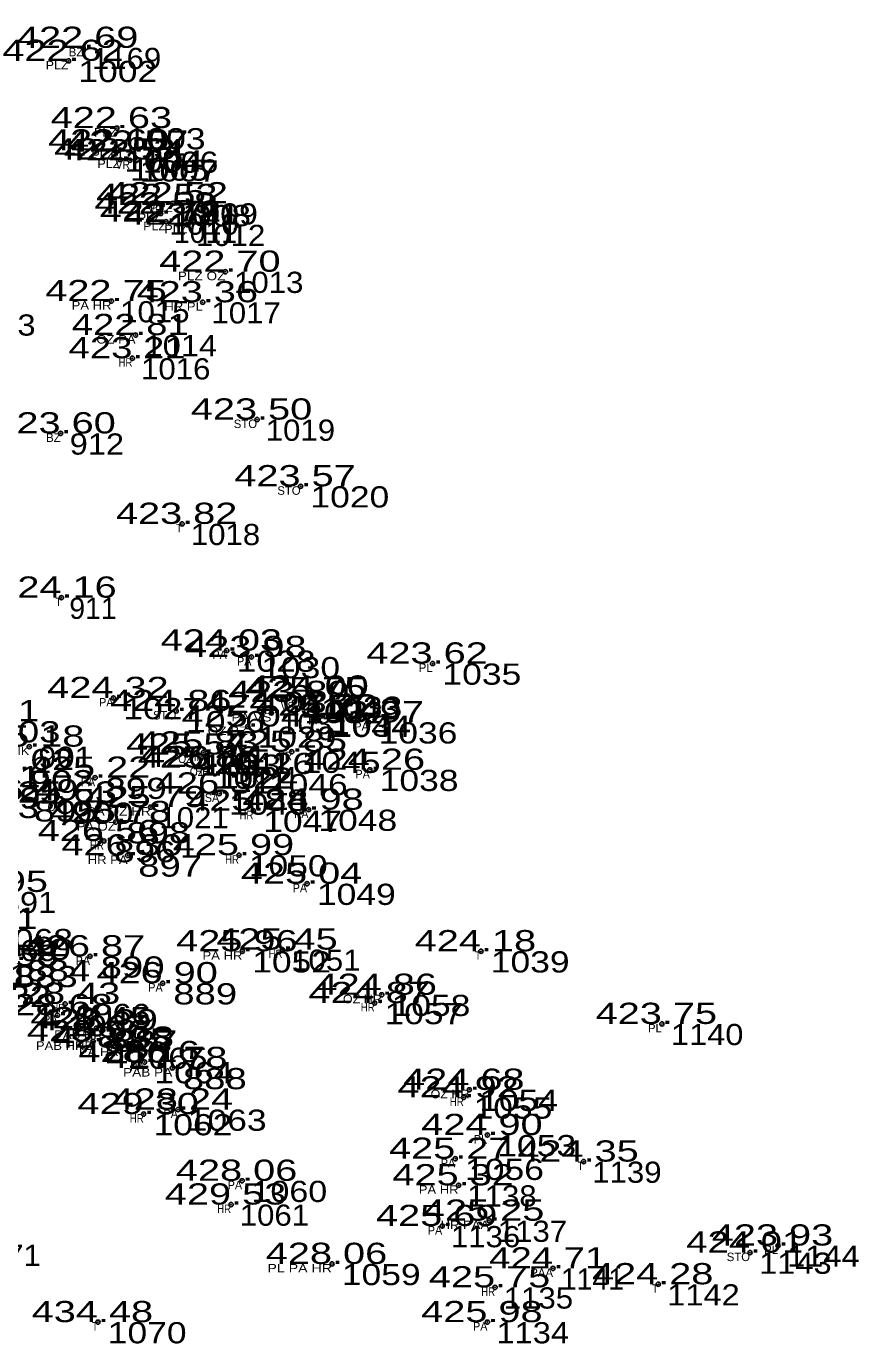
# Model space of a CAD drawing. Extents: x -639390 to -639074, y -1138747 to -1138358.
# Drawn here: x -639121.42 to -639091.98, y -1138695.49 to -1138648.89 of the extents above; entities that cross this region are included whole.
import ezdxf
from ezdxf.enums import TextEntityAlignment as Align

# ---------------------------------------------------------------- set-up
doc = ezdxf.new("R2010")
doc.units = 0
doc.header["$LTSCALE"] = 0.3
doc.header["$PDMODE"] = 32
doc.header["$PDSIZE"] = 0.15
for name, color, linetype in [('11', 7, 'Continuous'), ('12', 7, 'Continuous'), ('13', 7, 'Continuous'), ('57', 7, 'Continuous')]:
    doc.layers.add(name, color=color, linetype=linetype)

msp = doc.modelspace()

# ---------------------------------------------------------------- linework, layer by layer
at = {"layer": '11'}
for p in [(-639119.41, -1138649.65), (-639119.93, -1138650.11), (-639118.22, -1138652.49), (-639118.31, -1138653.28), (-639118.1, -1138653.6), (-639117.76, -1138653.63), (-639117.64, -1138653.32), (-639116.67, -1138655.51), (-639116.61, -1138655.21), (-639116.24, -1138655.15), (-639116.48, -1138655.8), (-639115.73, -1138655.91), (-639114.38, -1138657.57), (-639118.41, -1138658.61), (-639115.18, -1138658.65), (-639117.56, -1138659.81), (-639117.67, -1138660.63), (-639113.26, -1138662.8), (-639120.21, -1138663.29), (-639111.72, -1138665.16), (-639115.91, -1138666.49), (-639120.18, -1138669.1), (-639114.33, -1138670.97), (-639113.46, -1138671.2), (-639107.05, -1138671.43), (-639118.34, -1138672.65), (-639111.35, -1138672.66), (-639111.26, -1138672.6), (-639116.12, -1138673.11), (-639112.75, -1138673.18), (-639111.94, -1138672.79), (-639113.59, -1138673.66), (-639110.96, -1138673.28), (-639110.95, -1138673.27), (-639109.31, -1138673.51), (-639121.32, -1138674.37), (-639115.16, -1138674.58), (-639112.03, -1138674.55), (-639115.55, -1138674.65), (-639114.95, -1138675.09), (-639118.99, -1138675.47), (-639115.14, -1138675.11), (-639113.19, -1138675.34), (-639109.27, -1138675.19), (-639114.6, -1138676.03), (-639120.17, -1138676.35), (-639117.02, -1138676.51), (-639113.39, -1138676.64), (-639111.44, -1138676.6), (-639118.26, -1138677.04), (-639118.68, -1138677.71), (-639117.84, -1138678.22), (-639113.9, -1138678.21), (-639111.49, -1138679.22), (-639113.78, -1138681.61), (-639112.36, -1138681.55), (-639105.34, -1138681.61), (-639119.17, -1138681.79), (-639116.6, -1138682.74), (-639120.05, -1138683.47), (-639109.1, -1138683.44), (-639108.85, -1138683.15), (-639120.32, -1138683.87), (-639118.94, -1138684.33), (-639118.72, -1138684.41), (-639098.94, -1138684.18), (-639119.06, -1138684.8), (-639118.15, -1138685.02), (-639117.24, -1138685.53), (-639116.26, -1138685.74), (-639105.75, -1138686.51), (-639116.06, -1138687.21), (-639105.95, -1138686.78), (-639117.27, -1138687.37), (-639105.11, -1138688.11), (-639106.25, -1138688.95), (-639101.71, -1138689.05), (-639113.79, -1138689.73), (-639106.13, -1138689.89), (-639114.18, -1138690.57), (-639106.71, -1138691.33), (-639105.05, -1138691.14), (-639095.82, -1138692.27), (-639094.83, -1138692.02), (-639110.61, -1138692.67), (-639102.79, -1138692.83), (-639104.84, -1138693.5), (-639099.07, -1138693.39), (-639118.89, -1138694.73), (-639105.11, -1138694.73)]:
    msp.add_point(p, dxfattribs=at)

# ---------------------------------------------------------------- texts
at = {"layer": '12'}
for s, width, p in [('422.69 ', 1.4, (-639119.41, -1138649.65)), ('422.62 ', 1.4, (-639119.93, -1138650.11)), ('422.63 ', 1.4, (-639118.22, -1138652.49)), ('422.60 ', 1.4, (-639118.31, -1138653.28)), ('422.57 ', 1.4, (-639117.64, -1138653.32)), ('422.53 ', 1.4, (-639118.1, -1138653.6)), ('422.54 ', 1.4, (-639117.76, -1138653.63)), ('422.53 ', 1.4, (-639116.61, -1138655.21)), ('422.52 ', 1.4, (-639116.24, -1138655.15)), ('422.58 ', 1.4, (-639116.67, -1138655.51)), ('422.72 ', 1.4, (-639116.48, -1138655.8)), ('422.81 ', 1.35, (-639115.729, -1138655.91)), ('422.70 ', 1.4, (-639114.38, -1138657.57)), ('422.75 ', 1.4, (-639118.41, -1138658.61)), ('423.36 ', 1.4, (-639115.179, -1138658.65)), ('422.81 ', 1.35, (-639117.559, -1138659.81)), ('423.21 ', 1.35, (-639117.669, -1138660.63)), ('423.50 ', 1.4, (-639113.26, -1138662.8)), ('423.60 ', 1.4, (-639120.21, -1138663.29)), ('423.57 ', 1.4, (-639111.72, -1138665.16)), ('423.82 ', 1.4, (-639115.91, -1138666.49)), ('424.16 ', 1.4, (-639120.179, -1138669.1)), ('424.03 ', 1.4, (-639114.33, -1138670.97)), ('423.98 ', 1.4, (-639113.46, -1138671.2)), ('423.62 ', 1.4, (-639107.05, -1138671.43)), ('424.32 ', 1.4, (-639118.34, -1138672.65)), ('423.89 ', 1.4, (-639111.94, -1138672.79)), ('425.75 ', 1.4, (-639111.35, -1138672.66)), ('424.00 ', 1.4, (-639111.26, -1138672.6)), ('424.86 ', 1.4, (-639116.119, -1138673.11)), ('424.03 ', 1.4, (-639112.75, -1138673.18)), ('425.72 ', 1.4, (-639110.96, -1138673.28)), ('424.22 ', 1.4, (-639110.95, -1138673.27)), ('425.01 ', 1.35, (-639122.849, -1138673.47)), ('425.04 ', 1.4, (-639113.59, -1138673.66)), ('423.97 ', 1.4, (-639109.31, -1138673.51)), ('425.18 ', 1.4, (-639121.32, -1138674.37)), ('425.57 ', 1.4, (-639115.55, -1138674.65)), ('425.83 ', 1.4, (-639115.16, -1138674.58)), ('425.85 ', 1.4, (-639112.03, -1138674.55)), ('425.62 ', 1.4, (-639121.68, -1138675.2)), ('425.86 ', 1.4, (-639115.139, -1138675.11)), ('426.14 ', 1.4, (-639114.95, -1138675.09)), ('424.26 ', 1.4, (-639109.269, -1138675.19)), ('425.22 ', 1.4, (-639118.99, -1138675.47)), ('426.16 ', 1.4, (-639113.189, -1138675.34)), ('426.41 ', 1.35, (-639122.799, -1138675.81)), ('426.31 ', 1.35, (-639114.599, -1138676.03)), ('426.49 ', 1.4, (-639121.53, -1138676.27)), ('425.63 ', 1.4, (-639120.17, -1138676.35)), ('425.79 ', 1.4, (-639117.02, -1138676.51)), ('425.88 ', 1.4, (-639113.39, -1138676.64)), ('424.98 ', 1.4, (-639111.44, -1138676.6)), ('425.78 ', 1.4, (-639118.26, -1138677.04)), ('426.56 ', 1.4, (-639118.679, -1138677.71)), ('426.30 ', 1.4, (-639117.84, -1138678.22)), ('425.99 ', 1.4, (-639113.9, -1138678.21)), ('426.95 ', 1.4, (-639122.61, -1138679.51)), ('425.04 ', 1.4, (-639111.49, -1138679.22)), ('428.41 ', 1.35, (-639122.909, -1138680.82)), ('426.87 ', 1.4, (-639119.17, -1138681.79)), ('425.96 ', 1.4, (-639113.779, -1138681.61)), ('425.45 ', 1.4, (-639112.36, -1138681.55)), ('424.18 ', 1.4, (-639105.34, -1138681.61)), ('428.58 ', 1.4, (-639122.24, -1138682.13)), ('428.40 ', 1.4, (-639121.8, -1138681.92)), ('426.90 ', 1.4, (-639116.6, -1138682.74)), ('429.71 ', 1.35, (-639123.179, -1138682.83)), ('424.86 ', 1.4, (-639108.849, -1138683.15)), ('428.43 ', 1.4, (-639120.05, -1138683.47)), ('424.87 ', 1.4, (-639109.1, -1138683.44)), ('428.68 ', 1.4, (-639120.32, -1138683.87)), ('428.45 ', 1.4, (-639118.94, -1138684.33)), ('428.39 ', 1.4, (-639118.72, -1138684.41)), ('423.75 ', 1.4, (-639098.94, -1138684.18)), ('428.56 ', 1.4, (-639119.059, -1138684.8)), ('428.38 ', 1.4, (-639118.15, -1138685.02)), ('428.16 ', 1.4, (-639117.239, -1138685.53)), ('427.78 ', 1.4, (-639116.26, -1138685.74)), ('424.92 ', 1.4, (-639105.95, -1138686.78)), ('424.68 ', 1.4, (-639105.75, -1138686.51)), ('429.30 ', 1.4, (-639117.27, -1138687.37)), ('428.24 ', 1.4, (-639116.06, -1138687.21)), ('424.90 ', 1.4, (-639105.11, -1138688.11)), ('425.27 ', 1.4, (-639106.25, -1138688.95)), ('424.35 ', 1.4, (-639101.71, -1138689.05)), ('428.06 ', 1.4, (-639113.789, -1138689.73)), ('425.32 ', 1.4, (-639106.13, -1138689.89)), ('429.53 ', 1.4, (-639114.18, -1138690.57)), ('425.25 ', 1.4, (-639105.05, -1138691.14)), ('425.69 ', 1.4, (-639106.71, -1138691.33)), ('423.93 ', 1.4, (-639094.83, -1138692.02)), ('424.01 ', 1.35, (-639095.819, -1138692.27)), ('428.06 ', 1.4, (-639110.609, -1138692.67)), ('424.71 ', 1.35, (-639102.789, -1138692.83)), ('424.28 ', 1.4, (-639099.07, -1138693.39)), ('425.75 ', 1.4, (-639104.84, -1138693.5)), ('434.48 ', 1.4, (-639118.89, -1138694.73)), ('425.98 ', 1.4, (-639105.11, -1138694.73))]:
    msp.add_text(s, height=0.75, dxfattribs=dict(at, width=width)).set_placement(p, align=Align.CENTER)
at = {"layer": '13'}
for s, width, p in [(' 1169', 1.1, (-639119.41, -1138650.4)), (' 1002', 1.25, (-639119.93, -1138650.86)), (' 1003', 1.25, (-639118.22, -1138653.24)), (' 1004', 1.25, (-639118.31, -1138654.03)), (' 1006', 1.2, (-639117.64, -1138654.07)), (' 1005', 1.25, (-639118.1, -1138654.35)), (' 1007', 1.25, (-639117.76, -1138654.38)), (' 1008', 1.25, (-639116.61, -1138655.96)), (' 1009', 1.2, (-639116.24, -1138655.9)), (' 1010', 1.1, (-639116.67, -1138656.26)), (' 1012', 1.1, (-639115.73, -1138656.66)), (' 1013', 1.1, (-639114.38, -1138658.32)), (' 1015', 1.1, (-639118.41, -1138659.36)), (' 1017', 1.1, (-639115.18, -1138659.4)), (' 913', 1.15, (-639123.34, -1138659.83)), (' 1014', 1.15, (-639117.56, -1138660.56)), (' 1016', 1.1, (-639117.67, -1138661.38)), (' 1019', 1.1, (-639113.26, -1138663.55)), (' 912', 1.15, (-639120.21, -1138664.04)), (' 1020', 1.25, (-639111.72, -1138665.91)), (' 1018', 1.1, (-639115.91, -1138667.24)), (' 1028', 1.25, (-639114.33, -1138671.72)), (' 1030', 1.25, (-639113.46, -1138671.95)), (' 1035', 1.25, (-639107.05, -1138672.18)), (' 1027', 1.25, (-639118.34, -1138673.4)), (' 1043', 1.25, (-639111.35, -1138673.41)), (' 1033', 1.25, (-639111.26, -1138673.35)), (' 1026', 1.25, (-639116.12, -1138673.86)), (' 1032', 1.25, (-639111.94, -1138673.54)), (' 903', 1.35, (-639122.85, -1138674.22)), (' 1031', 1.1, (-639112.75, -1138673.93)), (' 1044', 1.25, (-639110.96, -1138674.03)), (' 1034', 1.25, (-639110.95, -1138674.02)), (' 1036', 1.25, (-639109.31, -1138674.26)), (' 1029', 1.25, (-639113.59, -1138674.41)), (' 901', 1.15, (-639121.32, -1138675.12)), (' 1045', 1.25, (-639112.03, -1138675.3)), (' 1023', 1.25, (-639115.55, -1138675.4)), (' 1042', 1.25, (-639115.16, -1138675.33)), (' 902', 1.35, (-639121.68, -1138675.95)), (' 899', 1.3, (-639118.99, -1138676.22)), (' 1022', 1.25, (-639115.14, -1138675.86)), (' 1024', 1.25, (-639114.95, -1138675.84)), (' 1046', 1.25, (-639113.19, -1138676.09)), (' 1038', 1.25, (-639109.27, -1138675.94)), (' 894', 1.35, (-639122.8, -1138676.56)), (' 893', 1.35, (-639123.61, -1138676.9)), (' 895', 1.35, (-639121.53, -1138677.02)), (' 900', 1.3, (-639120.17, -1138677.1)), (' 1040', 1.25, (-639114.6, -1138676.78)), (' 1021', 1.1, (-639117.02, -1138677.26)), (' 1047', 1.25, (-639113.39, -1138677.39)), (' 1048', 1.25, (-639111.44, -1138677.35)), (' 898', 1.35, (-639118.26, -1138677.79)), (' 896', 1.3, (-639118.68, -1138678.46)), (' 897', 1.35, (-639117.84, -1138678.97)), (' 1050', 1.25, (-639113.9, -1138678.96)), (' 1049', 1.25, (-639111.49, -1138679.97)), (' 891', 1.15, (-639122.61, -1138680.26)), (' 1068', 1.25, (-639122.91, -1138681.57)), (' 1069', 1.2, (-639123.33, -1138681.96)), (' 1051', 1.1, (-639112.36, -1138682.3)), (' 884', 1.35, (-639121.8, -1138682.67)), (' 890', 1.35, (-639119.17, -1138682.54)), (' 1052', 1.25, (-639113.78, -1138682.36)), (' 1039', 1.25, (-639105.34, -1138682.36)), (' 883', 1.35, (-639122.24, -1138682.88)), (' 882', 1.35, (-639123.18, -1138683.58)), (' 889', 1.35, (-639116.6, -1138683.49)), (' 1058', 1.25, (-639108.85, -1138683.9)), (' 1067', 1.25, (-639120.32, -1138684.62)), (' 1066', 1.2, (-639120.05, -1138684.22)), (' 1057', 1.25, (-639109.1, -1138684.19)), (' 885', 1.35, (-639118.94, -1138685.08)), (' 1140', 1.15, (-639098.94, -1138684.93)), (' 886', 1.35, (-639119.06, -1138685.55)), (' 887', 1.35, (-639118.72, -1138685.16)), (' 1065', 1.25, (-639118.15, -1138685.77)), (' 1064', 1.25, (-639117.24, -1138686.28)), (' 888', 1.35, (-639116.26, -1138686.49)), (' 1054', 1.25, (-639105.75, -1138687.26)), (' 1055', 1.25, (-639105.95, -1138687.53)), (' 1062', 1.25, (-639117.27, -1138688.12)), (' 1063', 1.25, (-639116.06, -1138687.96)), (' 1053', 1.25, (-639105.11, -1138688.86)), (' 1056', 1.25, (-639106.25, -1138689.7)), (' 1139', 1.1, (-639101.71, -1138689.8)), (' 1060', 1.2, (-639113.79, -1138690.48)), (' 1138', 1.1, (-639106.13, -1138690.64)), (' 1061', 1.1, (-639114.18, -1138691.32)), (' 1136', 1.1, (-639106.71, -1138692.08)), (' 1137', 1.1, (-639105.05, -1138691.89)), (' 1071', 1.1, (-639123.67, -1138692.74)), (' 1143', 1.15, (-639095.82, -1138693.02)), (' 1144', 1.15, (-639094.83, -1138692.77)), (' 1059', 1.25, (-639110.61, -1138693.42)), (' 1135', 1.1, (-639104.84, -1138694.25)), (' 1142', 1.15, (-639099.07, -1138694.14)), (' 1070', 1.25, (-639118.89, -1138695.48)), (' 1134', 1.15, (-639105.11, -1138695.48))]:
    msp.add_text(s, height=0.75, dxfattribs=dict(at, width=width)).set_placement(p)
for s, p in [(' 1011', (-639116.48, -1138656.55)), (' 911', (-639120.18, -1138669.85)), (' 1141', (-639102.79, -1138693.58))]:
    msp.add_text(s, height=0.75, dxfattribs=at).set_placement(p)
at = {"layer": '57'}
for s, p in [('BZ', (-639119.409, -1138649.95)), ('STO', (-639113.259, -1138663.1)), ('BZ', (-639120.209, -1138663.59)), ('STO', (-639111.719, -1138665.46)), ('PL', (-639107.049, -1138671.73)), ('BZ', (-639111.259, -1138672.9)), ('STO', (-639116.119, -1138673.41)), ('PL', (-639098.939, -1138684.48)), ('PL', (-639105.109, -1138688.41)), ('STO', (-639095.819, -1138692.57)), ('PL', (-639094.829, -1138692.32)), ('PAA', (-639102.79, -1138693.13))]:
    msp.add_text(s, height=0.3, dxfattribs=at).set_placement(p, align=Align.RIGHT)
for s, width, p in [('PLZ', 1.1, (-639119.929, -1138650.41)), ('PLZ', 1.1, (-639118.219, -1138652.79)), ('PLZ', 1.1, (-639118.309, -1138653.58)), ('PLZ', 1.1, (-639117.639, -1138653.62)), ('PLZ', 1.1, (-639118.099, -1138653.9)), ('VR', 0.9, (-639117.759, -1138653.93)), ('VR', 0.9, (-639116.609, -1138655.51)), ('PLZ', 1.1, (-639116.239, -1138655.45)), ('PLZ', 1.1, (-639116.669, -1138655.81)), ('PLZ', 1.1, (-639116.479, -1138656.1)), ('PLZ', 1.1, (-639115.729, -1138656.21)), ('PLZ OZ', 1.2, (-639114.379, -1138657.87)), ('PA HR', 1.15, (-639118.409, -1138658.91)), ('HR PL', 1.15, (-639115.179, -1138658.95)), ('OZ PA', 1.15, (-639117.56, -1138660.11)), ('HR', 0.85, (-639117.669, -1138660.93)), ('T', 0.85, (-639115.91, -1138666.79)), ('T', 0.85, (-639120.18, -1138669.4)), ('PA', 0.95, (-639114.33, -1138671.27)), ('PA', 0.95, (-639113.46, -1138671.5)), ('PA', 0.95, (-639118.34, -1138672.95)), ('HR', 0.85, (-639111.349, -1138672.96)), ('VS', 0.9, (-639111.94, -1138673.09)), ('PA VS', 1.2, (-639112.75, -1138673.48)), ('PA', 0.95, (-639110.95, -1138673.57)), ('HR', 0.85, (-639110.959, -1138673.58)), ('PA', 0.95, (-639109.31, -1138673.81)), ('OZ BZ', 1.2, (-639113.589, -1138673.96)), ('MEZNIK', 1.1, (-639121.319, -1138674.67)), ('HR', 0.85, (-639112.029, -1138674.85)), ('OZ', 0.9, (-639115.549, -1138674.95)), ('HR', 0.85, (-639115.159, -1138674.88)), ('PA', 0.95, (-639118.99, -1138675.77)), ('OZ', 0.9, (-639115.139, -1138675.41)), ('HR', 0.85, (-639114.949, -1138675.39)), ('HR', 0.85, (-639113.189, -1138675.64)), ('PA', 0.95, (-639109.27, -1138675.49)), ('OZ', 0.9, (-639120.169, -1138676.65)), ('SA', 0.95, (-639114.6, -1138676.33)), ('PA OZ HR', 1.2, (-639117.019, -1138676.81)), ('HR', 0.85, (-639113.389, -1138676.94)), ('PA', 0.95, (-639111.44, -1138676.9)), ('PA OZ', 1.15, (-639118.259, -1138677.34)), ('HR', 0.85, (-639118.679, -1138678.01)), ('HR PA', 1.15, (-639117.84, -1138678.52)), ('HR', 0.85, (-639113.899, -1138678.51)), ('PA', 0.95, (-639111.49, -1138679.52)), ('PA', 0.95, (-639119.17, -1138682.09)), ('PA HR', 1.15, (-639113.779, -1138681.91)), ('HR', 0.85, (-639112.359, -1138681.85)), ('T', 0.85, (-639105.34, -1138681.91)), ('PA', 0.95, (-639116.6, -1138683.04)), ('OZ HR', 1.1, (-639108.849, -1138683.45)), ('PA', 0.95, (-639120.32, -1138684.17)), ('HR', 0.85, (-639120.049, -1138683.77)), ('HR', 0.85, (-639109.099, -1138683.74)), ('HR', 0.85, (-639118.939, -1138684.63)), ('PAB HRB', 1.15, (-639119.059, -1138685.1)), ('PAB HR', 1.15, (-639118.719, -1138684.71)), ('PA HR', 1.15, (-639118.149, -1138685.32)), ('PAB PA', 1.2, (-639116.26, -1138686.04)), ('PA', 0.95, (-639117.24, -1138685.83)), ('OZ HR', 1.1, (-639105.749, -1138686.81)), ('HR', 0.85, (-639105.949, -1138687.08)), ('HR', 0.85, (-639117.269, -1138687.67)), ('PA', 0.95, (-639116.06, -1138687.51)), ('PA', 0.95, (-639106.25, -1138689.25)), ('T', 0.85, (-639101.71, -1138689.35)), ('PA', 0.95, (-639113.79, -1138690.03)), ('PA HR', 1.15, (-639106.129, -1138690.19)), ('HR', 0.85, (-639114.179, -1138690.87)), ('PA', 0.95, (-639106.71, -1138691.63)), ('HR PAA', 1.15, (-639105.05, -1138691.44)), ('PL PA HR', 1.25, (-639110.609, -1138692.97)), ('HR', 0.85, (-639104.839, -1138693.8)), ('T', 0.85, (-639099.07, -1138693.69)), ('T', 0.85, (-639118.89, -1138695.03)), ('PA', 0.95, (-639105.11, -1138695.03))]:
    msp.add_text(s, height=0.3, dxfattribs=dict(at, width=width)).set_placement(p, align=Align.RIGHT)

doc.saveas('drawing.dxf')
